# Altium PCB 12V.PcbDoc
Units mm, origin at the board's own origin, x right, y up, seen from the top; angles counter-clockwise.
Board outline 50 x 50 mm, 2 copper layers (Top Layer, Bottom Layer); 13 components, 11 nets, 35 pads, 0 vias.
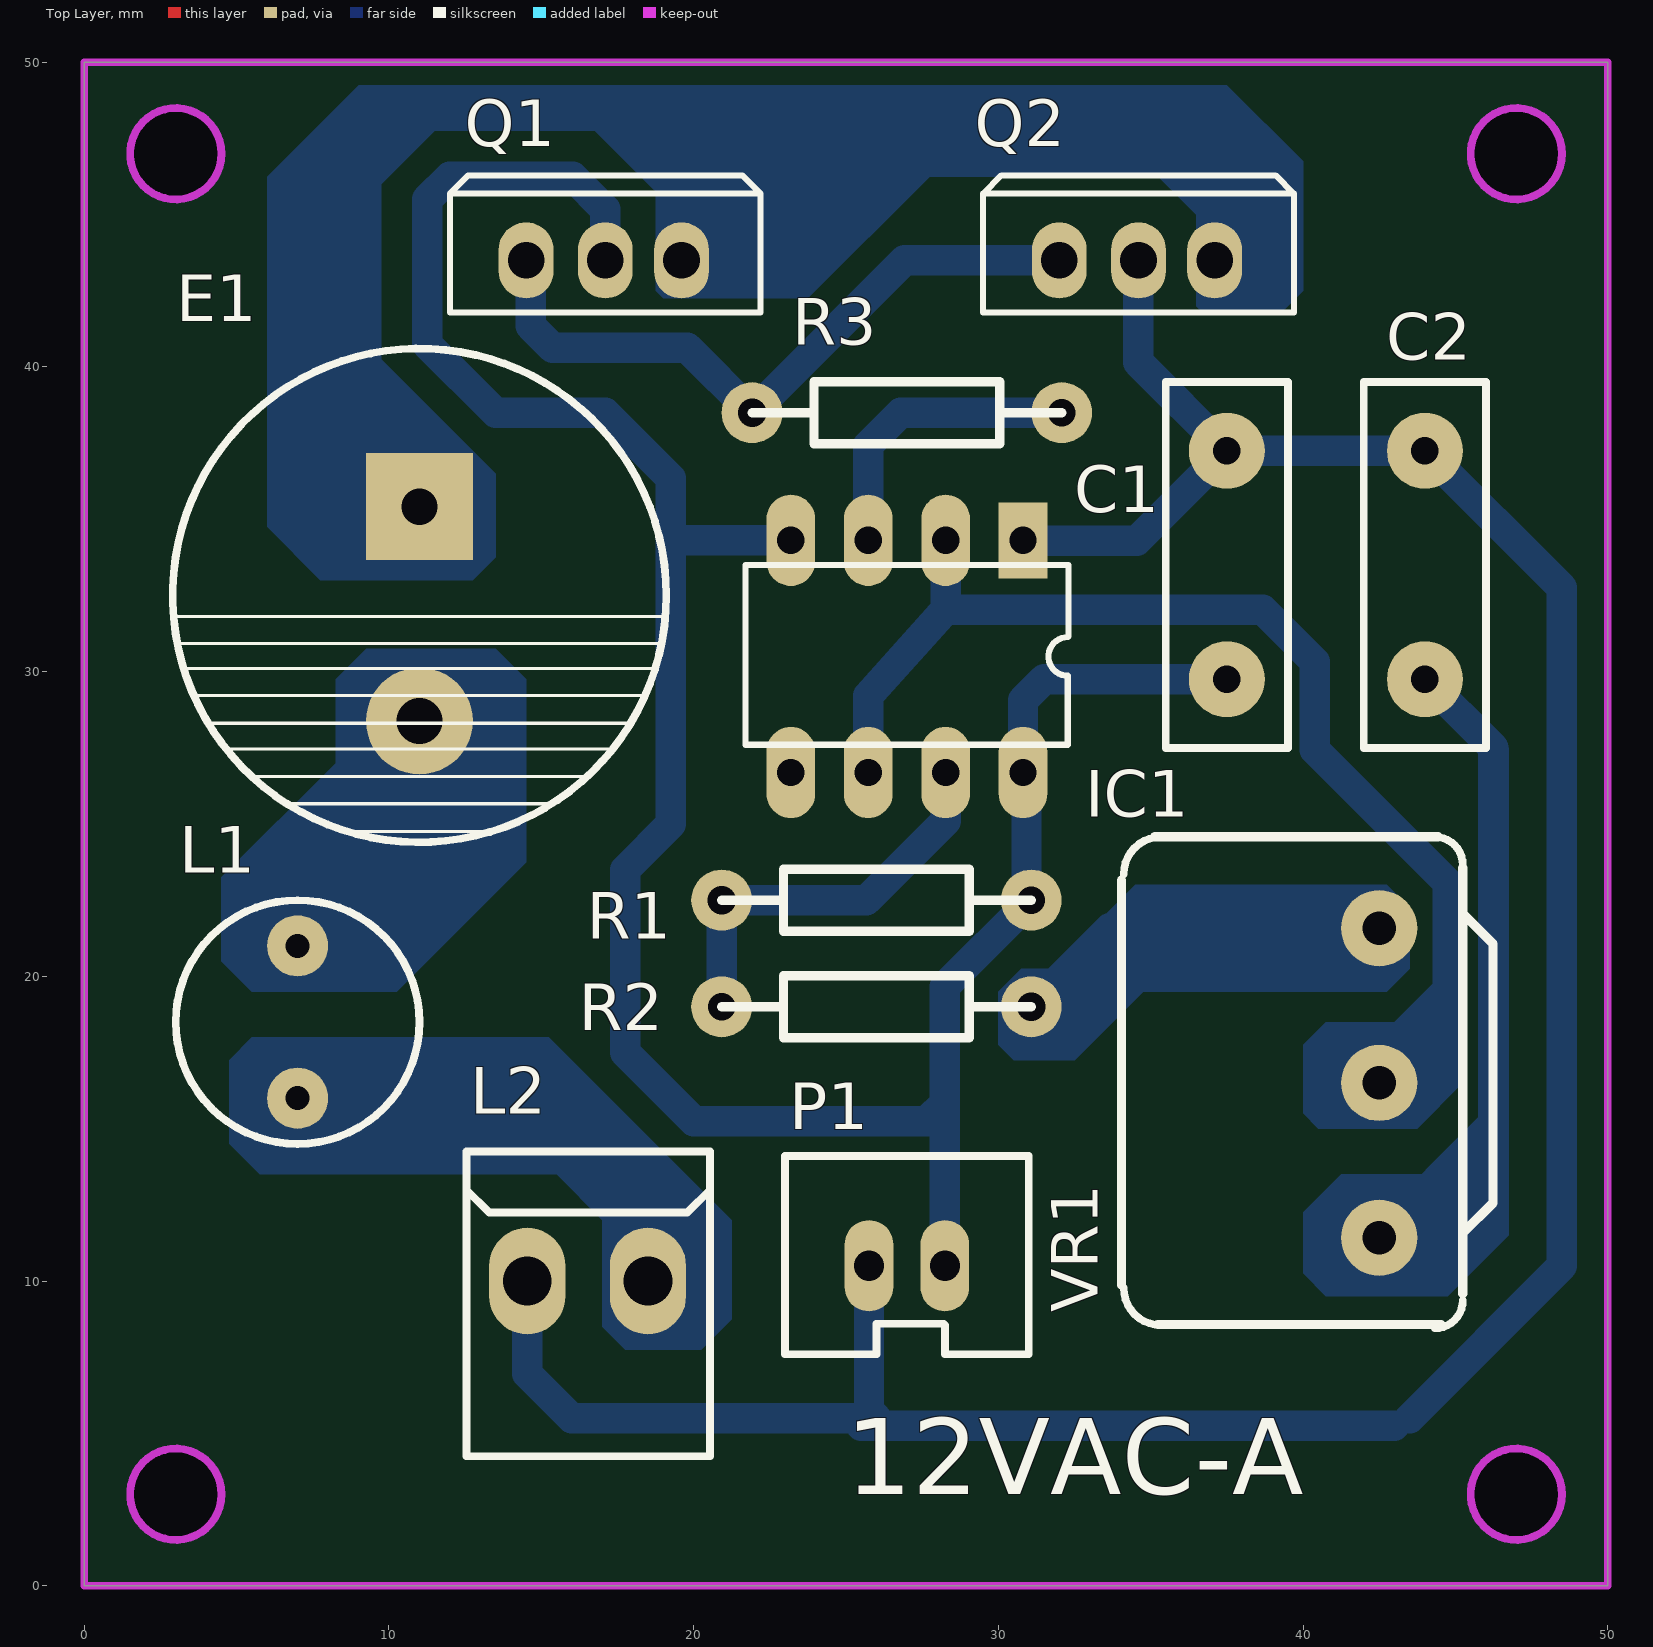
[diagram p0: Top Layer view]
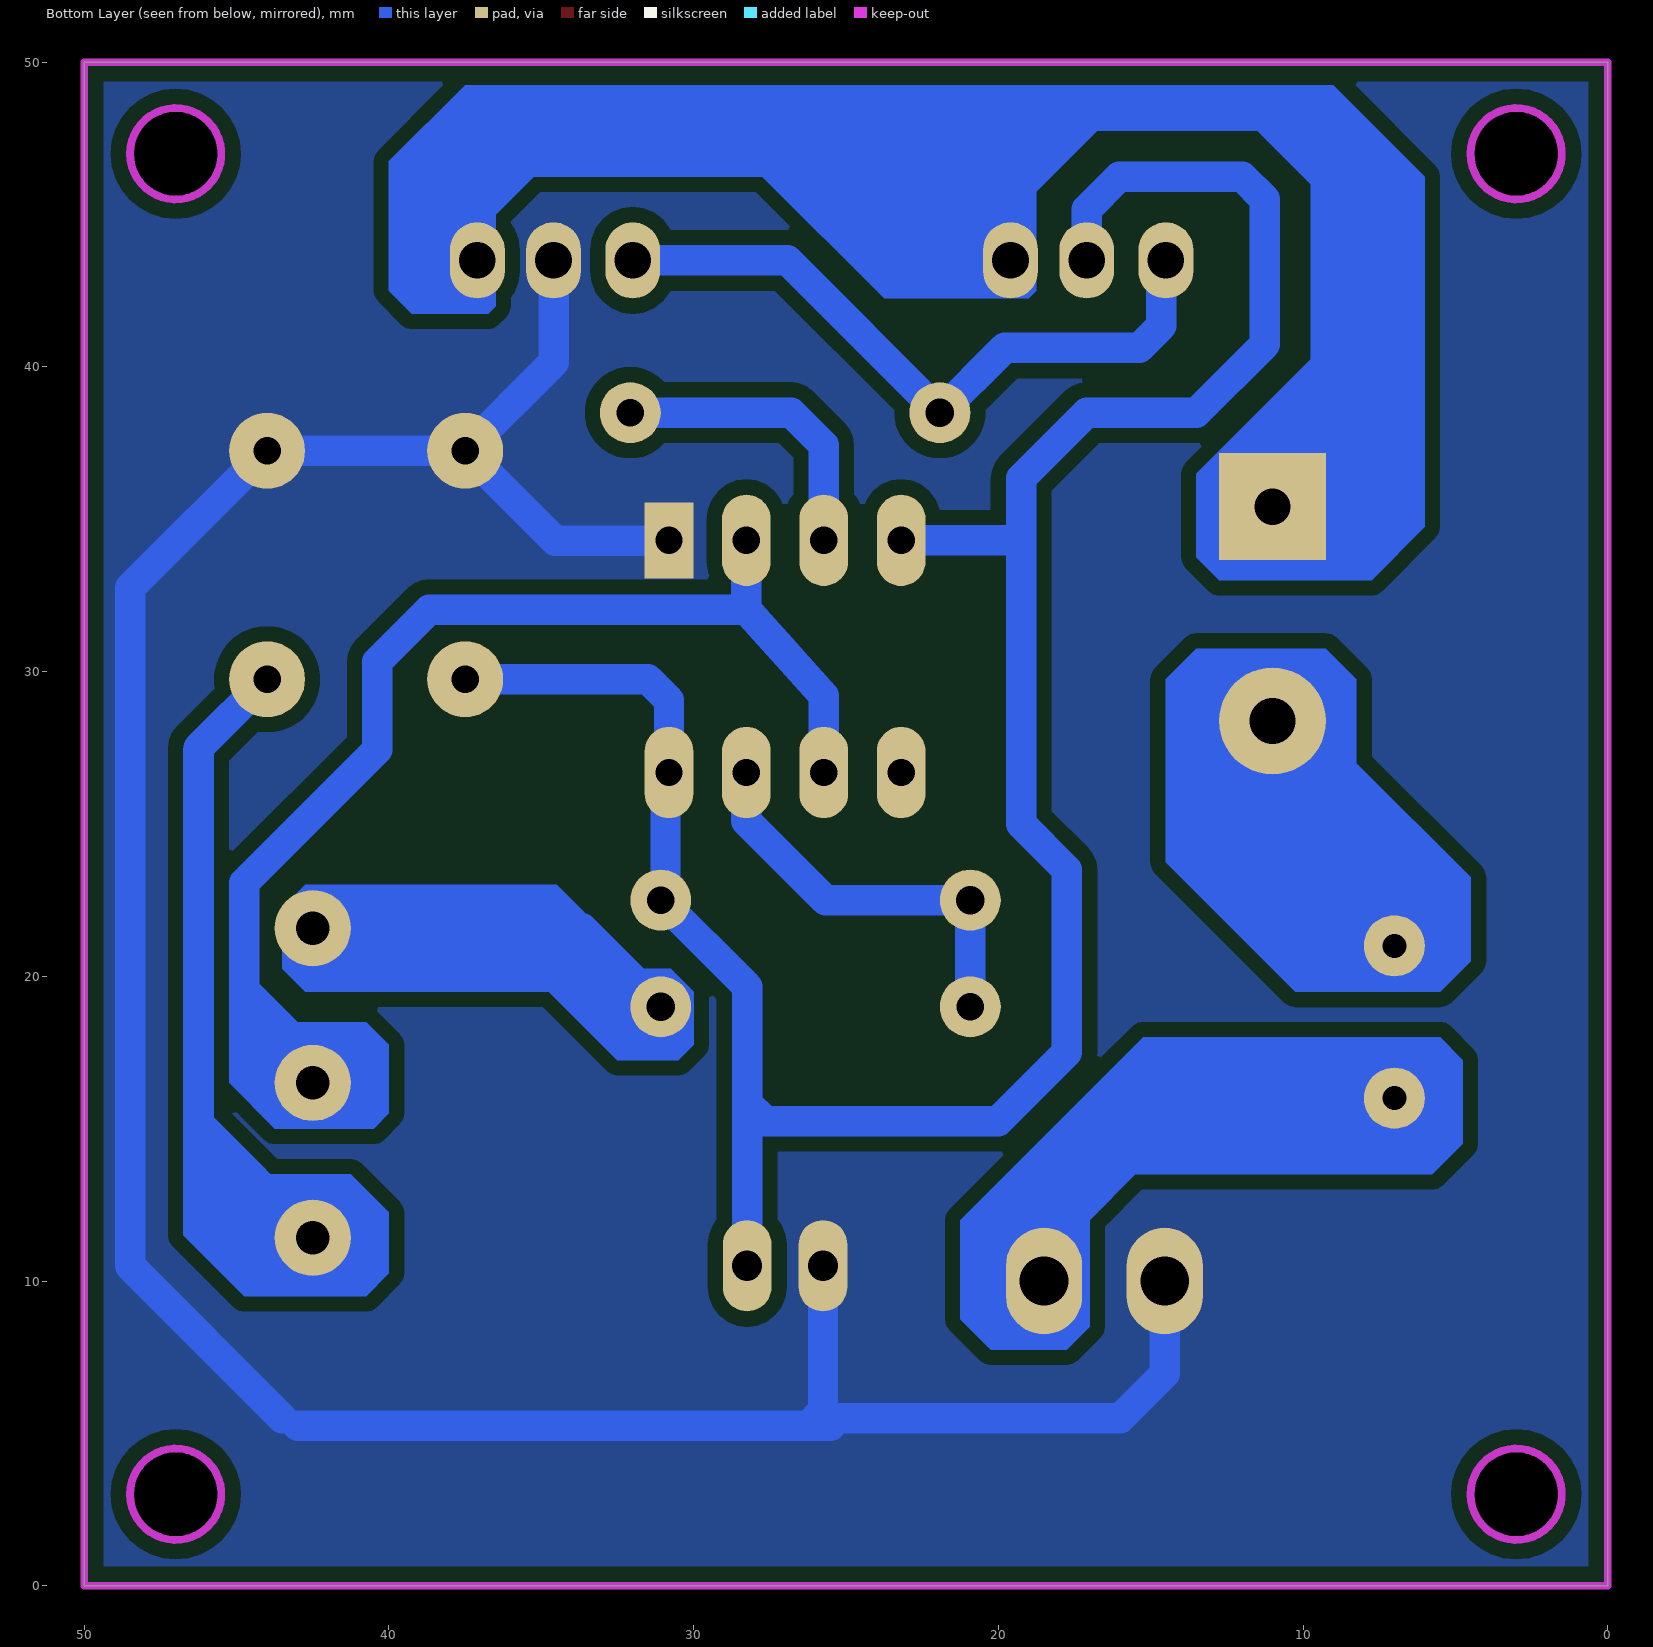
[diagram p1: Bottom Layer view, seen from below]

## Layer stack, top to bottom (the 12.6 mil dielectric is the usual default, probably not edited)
Top Solder: solder mask 0.0102, Solder Resist, Dk 3.5
Top Layer: signal copper 0.0356
Dielectric 1: dielectric 0.32, FR-4, Dk 4.8
Bottom Layer: signal copper 0.0356
Bottom Solder: solder mask 0.0102, Solder Resist, Dk 3.5

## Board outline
0,0 0,50 50,50 50,0
cut-out: 45.5,47 ccw(c47,47) 47,45.5 ccw(c47,47) 48.5,47 ccw(c47,47) 47,48.5 ccw(c47,47)
cut-out: 45.5,3 ccw(c47,3) 47,1.5 ccw(c47,3) 48.5,3 ccw(c47,3) 47,4.5 ccw(c47,3)
cut-out: 1.5,47 ccw(c3,47) 3,45.5 ccw(c3,47) 4.5,47 ccw(c3,47) 3,48.5 ccw(c3,47)
cut-out: 1.5,3 ccw(c3,3) 3,1.5 ccw(c3,3) 4.5,3 ccw(c3,3) 3,4.5 ccw(c3,3)

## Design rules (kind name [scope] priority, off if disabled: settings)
Clearance [All] p1: gap=0.5 ignorepadtopadclearanceinfootprint=FALSE
Height [All] p1: minheight=0 maxheight=55.4 prefheight=12.7
PolygonConnect [All] p1: connectstyle=Direct reliefconductorwidth=0.254 reliefentries=4 polygonreliefangle="90 Angle" airgapwidth=0.254
RoutingLayers [All] p1: top layer_v5=FALSE bottom layer_v5=TRUE
RoutingVias [All] p1: holewidth=0.711 width=1.27 viastyle="Through Hole" minholewidth=0.711 minwidth=1.27 maxholewidth=0.711 maxwidth=1.27
SilkToSilkClearance [All] p1: silktosilkclearance=0
SilkToSolderMaskClearance [IsPad] p1: minsilkscreentomaskgap=0 clearancetoexposedcopper=TRUE
SolderMaskExpansion [All] p1: expansion=0.102 istentingtop=FALSE
Width [All] p1: maxlimit=1 minlimit=1 preferedwidth=1
26 further rules are at their usual default settings.

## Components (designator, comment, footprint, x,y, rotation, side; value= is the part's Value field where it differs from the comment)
C1 "104" C7.5 37.5,33.5 r90 top
C2 "104" C7.5 44,33.5 r90 top
E1 "2200UF/25V" E16 11,32.5 r270 top
IC1 "NE555" DIP8 27,30.5 r270 top
L1 "1UH" H8 7,18.5 r270 top
L2 "12AC" 2P-3.96 16.54,10 r0 top
P1 "12V" 2PIN 27,10.5 r0 top
Q1 "TIP41A" TO220 17.1,43.492 r0 top
Q2 "TIP42A" TO220 34.6,43.492 r0 top
R1 "10K" R 26,22.5 r180 top
R2 "10K" R 26,19 r0 top
R3 "100" R 27,38.5 r180 top
VR1 "B50K" VR1 42.5,16.5 r90 top

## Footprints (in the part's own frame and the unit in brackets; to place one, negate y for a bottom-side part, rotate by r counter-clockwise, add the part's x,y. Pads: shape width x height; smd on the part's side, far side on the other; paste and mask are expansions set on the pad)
2P-3.96 [mm]
  oval 2.5x3.5 hole 1.6: 1(-2,0) 2(1.96,0)
  silkscreen extent -4,-5.75 4,4.25, body extent -3.86,-5.2 4.06,4.74, height 13.9
2PIN [mil]
  oval 62.99x118 hole 39: 1(-49,0) 2(49,0)
  silkscreen extent -157,-114 157,142, body extent -146,-106 146,134, height 276
C7.5 [mil]
  round 98 hole 35.43: 1(-147.64,0) 2(147.64,0)
  silkscreen extent -236,-79 237,79, body extent -226,-98 226,98, height 98
DIP8 [mm]
  rect 2.489x1.6 hole 0.9: 1(-3.81,3.81)
  oval 2.997x1.6 hole 0.9: 2(-3.81,1.27) 3(-3.81,-1.27) 4(-3.81,-3.81) 5(3.81,-3.81) 6(3.81,-1.27) 7(3.81,1.27) 8(3.81,3.81)
  silkscreen extent -3,-5.3 2.9,5.3, body extent -3.98,-5.4 3.78,5.4, height 4.5
E16 [mil]
  rect 138x138 hole 47: 1(-114.88,0)
  round 138 hole 59: 2(162.12,0)
  silkscreen extent -319,-319 319,319, body extent -291,-315 347,323, height 1004
H8 [mil]
  round 79 hole 31: 1(-98.43,0) 2(98.43,0)
  silkscreen extent -157,-157 157,157, body extent -157,-157 157,157, height 394
R [mm]
  round 2 hole 0.94: 1(5.08,0)
  round 2 hole 0.9: 2(-5.08,0)
  silkscreen extent -5.08,-1.02 5.08,1.02, body extent -5.3,-1.3 5.46,1.22, height 3.26
TO220 [mm]
  oval 1.8x2.5 hole 1.2: b(-2.6,0.008) c(0,0.008) e(2.5,0.008)
  silkscreen extent -5.1,-1.7 5.1,2.8, body extent -5.1,-1.7 5.1,2.8, height 25.5
VR1 [mm]
  round 2.5 hole 1.1: 1(5.08,0) 2(-5.08,0) W1(0,0)
  silkscreen extent -8.05,-3.73 8.08,8.46, body extent -8.6,-33.3 8.4,7.55, height 21

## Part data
C1 C2: library part C
E1: library part E
L1: library part L
P1: library part 2PIN
Q1: library part NPN
Q2: library part PNP
R1 R2 R3: library part R
VR1: library part VR1

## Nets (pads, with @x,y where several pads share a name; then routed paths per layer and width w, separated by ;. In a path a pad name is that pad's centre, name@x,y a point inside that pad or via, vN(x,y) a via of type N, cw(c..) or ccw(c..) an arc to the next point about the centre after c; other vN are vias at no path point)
+12: C1.1 IC1.4 IC1.8 P1.2 Q1.c R1.2 | length 84.8
  Bottom Layer w1: Q1.c 17.1,45.17 16.028,46.243 11.993,46.243 11.25,45.5 11.25,40.75 13.5,38.5 17.1,38.5 19.25,36.35 19.25,34.25 ; IC1.4 19.31,34.31 19.25,34.25 ; P1.2 28.245,15.836 ; C1.1 31.5,29.75 30.81,29.06 IC1.8 30.925,26.575 30.925,22.655 R1.2 28.245,19.665 28.245,15.836 ; 19.25,34.25 19.25,25 17.75,23.5 17.75,17.5 20,15.25 27.659,15.25 28.245,15.836
GND: C1.2 C2.2 IC1.1 L2.1 P1.1 Q2.c | length 95.3
  Bottom Layer w1: L2.1 14.54,6.96 16,5.5 26,5.5 25.755,5.745 P1.1 ; 25.5,5.25 43,5.25 ; IC1.1 30.81,34.292 34.542,34.292 C1.2 ; Q2.c 34.6,40.15 C1.2 ; 43.5,5.5 48.5,10.5 48.5,32.75 C2.2 C1.2
NetC2_1: C2.1 VR1.2 | length 20.8
  Bottom Layer w1: VR1.2 46.25,15.17 46.25,27.5 C2.1
NetE1_1: E1.1 Q1.e Q2.e | length 48.7
  Bottom Layer w1: E1.1 11,37.25 8.5,39.75 8.5,46 11,48.5 17.008,48.5 19.6,45.908 Q1.e@19.6,43.843 ; Q1.e Q1.e@19.6,43.843 ; Q2.e 37.1,45.57 35.728,46.942 27.203,46.942 24.104,43.843 Q1.e@19.6,43.843
NetE1_2: E1.2 L1.1 | length 9
  Bottom Layer w1: L1.1 11,25 E1.2
NetIC1_2: IC1.2 IC1.6 VR1.W1 | length 38
  Bottom Layer w1: IC1.6 25.73,29.212 28.27,32.032 ; IC1.2 28.27,32.032 ; VR1.W1 44.75,18.75 44.75,23.07 40.385,27.434 40.385,30.33 38.683,32.032 28.27,32.032
NetIC1_3: IC1.3 R3.2 | length 9.9
  Bottom Layer w1: IC1.3 25.73,37.433 26.797,38.5 R3.2
NetIC1_7: IC1.7 R1.1 R2.2 | length 13.5
  Bottom Layer w1: R2.2 R1.1 25.672,22.5 28.27,25.098 IC1.7
NetL1_2: L1.2 L2.2 | length 15.7
  Bottom Layer w1: L1.2 15.5,16 18.5,13 L2.2
NetQ1_B: Q1.b Q2.b R3.1 | length 22.8
  Bottom Layer w1: Q1.b 14.653,43.347 14.653,41.347 15.375,40.625 19.795,40.625 R3.1 26.92,43.5 Q2.b
NetR2_1: R2.1 VR1.1 | length 12.5
  Bottom Layer w1: R2.1 33.66,21.58 VR1.1
pads on no net: IC1.5

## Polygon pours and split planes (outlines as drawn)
GND on Bottom Layer "NONET_L02_P-001" (solid, remove dead copper, pour order 0): 0,0 50,0 49.75,0.25 49.75,50 0,50

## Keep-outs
Keep-Out Layer:
  circle w0.254: c47,47 r1.5
  circle w0.254: c47,3 r1.5
  circle w0.254: c3,47 r1.5
  circle w0.254: c3,3 r1.5
  lines w0.254: 0,0 50,0 50,50 0,50 0,0

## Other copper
Bottom Layer:
  region net NetR2_1: 32.5,17.25 34.75,19.5 42.75,19.5 43.5,20.25 43.5,22.25 42.75,23 34.5,23 31.75,20.25 30.75,20.25 30,19.5 30,17.75 30.5,17.25 31.5,17.25
  region net NetIC1_2: 45.25,20 45.25,16.5 43.75,15 40.5,15 40,15.5 40,17.75 40.75,18.5 43,18.5 44.5,20 44.75,20
  region net NetC2_1: 46.75,11.5 44.75,9.5 40.75,9.5 40,10.25 40,12.25 41.25,13.5 44.5,13.5 45.75,14.75 45.75,27.75 46.5,27.75 46.75,27.5
  region net NetE1_1: 13.5,33.75 13.5,36.5 9.75,40.25 9.75,46 11.5,47.75 16.75,47.75 18.75,45.75 18.75,42.5 19,42.25 23.75,42.25 27.75,46.25 35.25,46.25 36.5,45 36.5,42 36.75,41.75 39.25,41.75 40,42.5 40,46.75 37.5,49.25 9,49.25 6,46.25 6,34.75 7.75,33 12.75,33
  region net NetL1_2: 15.5,13.5 17,12 17,8.5 17.75,7.75 20.25,7.75 21.25,8.75 21.25,12 15.25,18 5.5,18 4.75,17.25 4.75,14.5 5.75,13.5 7.5,13.5
  region net NetE1_2: 10.25,19.5 14.5,23.75 14.5,29.75 13.5,30.75 9.25,30.75 8.25,29.75 8.25,27 4.5,23.25 4.5,20.5 5.5,19.5 7,19.5

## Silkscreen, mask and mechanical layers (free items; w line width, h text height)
Top Overlay:
  text "12VAC-A" at 25,3 h2.5
Bottom Solder:
  lines w2: 7,16 15,16 18.5,12.5 18.5,10 ; 7,21 8.75,21 11,23.25 11,28.5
